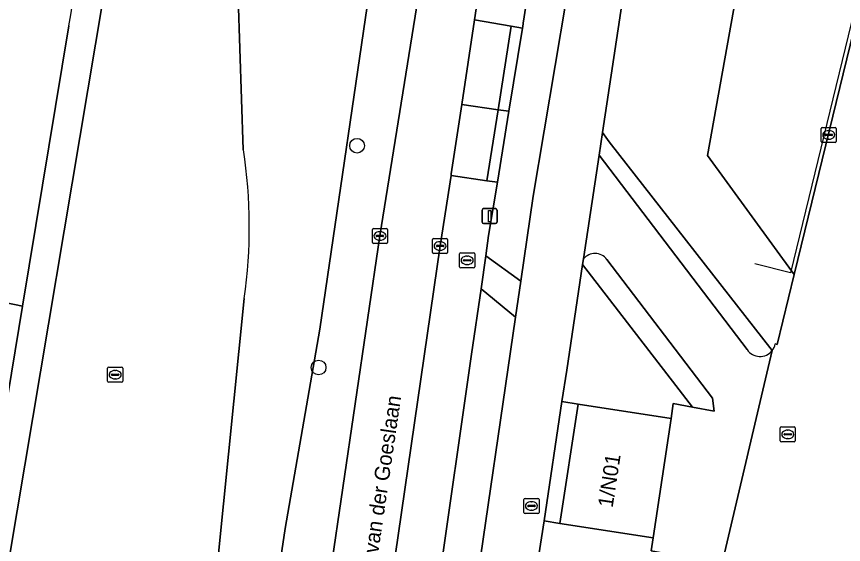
# Model space of a CAD drawing. Extents: x 163043 to 165076, y 382019 to 382874.
# Drawn here: x 163119.9 to 163174.8, y 382777.8 to 382812.9 of the extents above; entities that cross this region are included whole.
import ezdxf

# ---------------------------------------------------------------- set-up
doc = ezdxf.new("R2010")
doc.units = 0
for name, color, linetype in [('IMGEO_Berm_groen', 7, 'Continuous'), ('IMGEO_Berm_halfverhard', 7, 'Continuous'), ('IMGEO_Boom', 7, 'Continuous'), ('IMGEO_Brandkraan', 7, 'Continuous'), ('IMGEO_Erf', 7, 'Continuous'), ('IMGEO_Fietspad_gesloten', 7, 'Continuous'), ('IMGEO_Fietspad_open', 7, 'Continuous'), ('IMGEO_Groenvoorziening', 7, 'Continuous'), ('IMGEO_Hek', 7, 'Continuous'), ('IMGEO_Kolk', 7, 'Continuous'), ('IMGEO_Lichtmast', 7, 'Continuous'), ('IMGEO_Openbare_ruimte_label', 7, 'Continuous'), ('IMGEO_Pand', 7, 'Continuous'), ('IMGEO_Pand_nummerreeks', 7, 'Continuous'), ('IMGEO_Parkeervlak_open', 7, 'Continuous'), ('IMGEO_Rijbaan_lokaal_gesloten', 7, 'Continuous'), ('IMGEO_Rijbaan_lokaal_open', 7, 'Continuous'), ('IMGEO_Rioolput', 7, 'Continuous'), ('IMGEO_Voetpad_halfverhard', 7, 'Continuous'), ('IMGEO_Voetpad_open', 7, 'Continuous')]:
    doc.layers.add(name, color=color, linetype=linetype)

msp = doc.modelspace()

# ---------------------------------------------------------------- linework, layer by layer
at = {"layer": 'IMGEO_Berm_groen'}
for points in [[(163144.059, 382798.28), (163147.602, 382820.471), (163149.65, 382831.634), (163150.516, 382836.357), (163150.728, 382837.512), (163148.179, 382837.97), (163148.999, 382842.523)], [(163135.699, 382830.541), (163137.058, 382838.452), (163135.555, 382839.712), (163129.752, 382841.072), (163125.716, 382814.214), (163119.444, 382776.857), (163117.196, 382766.95)], [(163144.103, 382835.721), (163143.26, 382822.615), (163143.707, 382817.037), (163140.066, 382792.087), (163137.776, 382778.86), (163133.466, 382750), (163130.056, 382727.169), (163128.37, 382716.411), (163130.927, 382716.032), (163131.494, 382720.017), (163132.583, 382726.924)], [(163135.056, 382794.132), (163131.605, 382759.828), (163131.17, 382753.793), (163131.079, 382750), (163130.908, 382742.92), (163130.056, 382727.169), (163133.466, 382750), (163137.776, 382778.86), (163140.066, 382792.087), (163143.707, 382817.037), (163143.26, 382822.615), (163144.103, 382835.721)], [(163134.992, 382804.003), (163134.545, 382817.473)], [(163134.545, 382817.473), (163134.992, 382804.003)], [(163117.196, 382766.95), (163119.444, 382776.857), (163125.716, 382814.214)], [(163114.939, 382798.525), (163114.915, 382798.417), (163114.168, 382794.935), (163115.63, 382794.599), (163120.341, 382793.612), (163123.418, 382812.236)], [(163123.418, 382812.236), (163120.341, 382793.612), (163118.136, 382780.262)], [(163133.078, 382728.993), (163133.75, 382730.587), (163134.348, 382732.415), (163134.652, 382734.165), (163134.996, 382736.383), (163136.998, 382750), (163137.687, 382754.683), (163140.785, 382775.983), (163144.059, 382798.28)], [(163118.136, 382780.262), (163120.341, 382793.612), (163115.63, 382794.599), (163108.285, 382760.577), (163100.666, 382724.498), (163102.091, 382725.758)], [(163128.054, 382714.322), (163128.37, 382716.411), (163130.056, 382727.169), (163130.908, 382742.92), (163131.079, 382750), (163131.17, 382753.793), (163131.605, 382759.828), (163135.056, 382794.132)]]:
    msp.add_lwpolyline(points, dxfattribs=at)
for points in [[(163157.332, 382836.53), (163154.718, 382836.977), (163154.482, 382835.678), (163153.583, 382830.888), (163150.907, 382816.447), (163150.331, 382812.628), (163152.761, 382812.211), (163153.515, 382812.081), (163153.528, 382812.16), (163153.568, 382812.405)], [(163150.138, 382790.439), (163150.763, 382794.772), (163151.077, 382796.956), (163151.271, 382798.302), (163151.849, 382801.853), (163151.156, 382801.951), (163148.773, 382802.288), (163148.045, 382797.616), (163144.417, 382772.599), (163146.726, 382772.31), (163147.509, 382772.212), (163147.935, 382775.112)]]:
    msp.add_lwpolyline(points, close=True, dxfattribs=at)
for centre, radius, start, end in [((163009.489, 382831.398), 115.53, 350.45256, 356.35077), ((163009.489, 382831.398), 115.53, 350.45256, 356.35077), ((163101.746, 382798.852), 33.643, 351.9354, 8.8075), ((163101.746, 382798.852), 33.643, 351.9354, 8.8075)]:
    msp.add_arc(centre, radius, start, end, dxfattribs=at)
at = {"layer": 'IMGEO_Berm_halfverhard'}
for points in [[(163159.263, 382804.526), (163158.823, 382805.145), (163158.596, 382803.635), (163168.418, 382790.74)], [(163170.081, 382790.666), (163159.263, 382804.526)], [(163157.56, 382796.752), (163157.504, 382796.382), (163163.68, 382788.362), (163164.793, 382786.917), (163166.223, 382786.643), (163166.127, 382787.521), (163159.112, 382796.727)]]:
    msp.add_lwpolyline(points, dxfattribs=at)
for centre, radius, start, end in [((163158.326, 382796.131), 0.986, 37.1943, 140.96), ((163169.276, 382791.301), 1.025, 213.1917, 321.7126)]:
    msp.add_arc(centre, radius, start, end, dxfattribs=at)
at = {"layer": 'IMGEO_Boom'}
for centre in [(163142.541, 382804.272), (163139.988, 382789.546)]:
    msp.add_circle(centre, 0.489, dxfattribs=at)
at = {"layer": 'IMGEO_Brandkraan'}
for p, q in [((163153.685, 382780.853), (163154.537, 382780.853)), ((163153.61, 382779.927), (163153.61, 382780.779)), ((163153.869, 382780.347), (163153.869, 382780.359)), ((163154.307, 382780.31), (163153.909, 382780.31)), ((163153.912, 382780.396), (163154.31, 382780.396)), ((163154.098, 382780.633), (163154.123, 382780.633)), ((163154.353, 382780.359), (163154.353, 382780.347)), ((163154.611, 382780.779), (163154.611, 382779.927)), ((163154.537, 382779.853), (163153.685, 382779.853)), ((163154.121, 382780.073), (163154.096, 382780.073))]:
    msp.add_line(p, q, dxfattribs=at)
for points in [[(163153.685, 382780.853), (163154.537, 382780.853)], [(163153.61, 382779.927), (163153.61, 382780.779)], [(163154.611, 382780.779), (163154.611, 382779.927)], [(163154.537, 382779.853), (163153.685, 382779.853)]]:
    msp.add_lwpolyline(points, dxfattribs=at)
for centre, radius, start, end in [((163153.687, 382780.777), 0.0765, 91.552, 178.448), ((163153.687, 382780.777), 0.0765, 91.552, 178.448), ((163154.535, 382780.777), 0.0765, 1.552, 88.448), ((163154.535, 382780.777), 0.0765, 1.552, 88.448), ((163153.909, 382780.356), 0.0403, 85.8775, 175.7526), ((163153.906, 382780.346), 0.0366, 178.938, 274.7102), ((163154.31, 382780.353), 0.043, 264.8664, 352.4533), ((163154.314, 382780.358), 0.0386, 1.7309, 96.639), ((163153.687, 382779.929), 0.0765, 181.552, 268.448), ((163153.687, 382779.929), 0.0765, 181.552, 268.448), ((163154.535, 382779.929), 0.0765, 271.552, 358.448), ((163154.535, 382779.929), 0.0765, 271.552, 358.448)]:
    msp.add_arc(centre, radius, start, end, dxfattribs=at)
for centre, major_axis, ratio, start_param, end_param in [((163154.097, 382780.353), (-0.387, 0.002), 0.722429, 4.712389, 7.853982), ((163154.122, 382780.353), (-0.39, 0.002), 0.717154, 1.570796, 4.712389)]:
    msp.add_ellipse(centre, major_axis=major_axis, ratio=ratio, start_param=start_param, end_param=end_param, dxfattribs=at)
at = {"layer": 'IMGEO_Erf'}
for points in [[(163360.605, 382802.831), (163320.187, 382810.107), (163314.649, 382811.104), (163314.256, 382811.175), (163314.349, 382812.183), (163260.669, 382823.114), (163260.43, 382821.928), (163260.281, 382821.959), (163252.701, 382823.524), (163242.427, 382825.645), (163242.333, 382825.25), (163240.001, 382825.677), (163241.323, 382832.305), (163232.097, 382834.207), (163234.481, 382827.114), (163183.142, 382837.726), (163182.274, 382837.906), (163182.21, 382837.622), (163181.791, 382837.701), (163171.545, 382795.713), (163170.414, 382791.078), (163170.285, 382791.115)], [(163170.081, 382790.666), (163166.826, 382776.841), (163169.382, 382776.239), (163169.071, 382774.966), (163168.15, 382770.94), (163167.891, 382771.003), (163167.468, 382769.275), (163156.035, 382722.526), (163161.495, 382721.157), (163163.241, 382720.719), (163175.878, 382717.552), (163198.326, 382728.588), (163200.211, 382729.514), (163222.075, 382740.263), (163242.58, 382750), (163320.843, 382788.378)]]:
    msp.add_lwpolyline(points, dxfattribs=at)
msp.add_arc((163169.266, 382791.307), 1.037, 321.8058, 349.3255, dxfattribs=at)
at = {"layer": 'IMGEO_Fietspad_gesloten'}
for points in [[(163160.254, 382840.645), (163160.864, 382844.839), (163161.113, 382845.228), (163163.828, 382857.821), (163161.411, 382858.355), (163161.217, 382857.454), (163158.619, 382845.314), (163158.416, 382844.084), (163158.129, 382842.056), (163157.76, 382839.448), (163157.671, 382838.945), (163157.332, 382836.53), (163153.568, 382812.405), (163153.528, 382812.16), (163153.515, 382812.081), (163152.616, 382806.559), (163151.849, 382801.853), (163151.271, 382798.302), (163151.077, 382796.956), (163153.406, 382795.273), (163154.228, 382800.916), (163156.415, 382813.95)], [(163150.245, 382773.595), (163153.058, 382792.885), (163150.763, 382794.772), (163150.138, 382790.439), (163147.935, 382775.112), (163147.509, 382772.212), (163145.195, 382756.443), (163143.08, 382742.3), (163139.573, 382718.665), (163139.22, 382715.736), (163138.911, 382713.773), (163141.421, 382713.325), (163141.748, 382715.527), (163143.616, 382727.869), (163147.259, 382753.463)]]:
    msp.add_lwpolyline(points, close=True, dxfattribs=at)
at = {"layer": 'IMGEO_Fietspad_open'}
msp.add_lwpolyline([(163153.406, 382795.273), (163151.077, 382796.956), (163150.763, 382794.772), (163153.058, 382792.885)], close=True, dxfattribs=at)
at = {"layer": 'IMGEO_Groenvoorziening'}
for points in [[(163173.417, 382846.227), (163168.902, 382847.136), (163167.534, 382847.364), (163167.195, 382845.104), (163164.825, 382845.479), (163161.538, 382823.186), (163158.823, 382805.145), (163159.263, 382804.526), (163170.081, 382790.666)], [(163170.285, 382791.115), (163170.414, 382791.078), (163171.545, 382795.713), (163165.783, 382803.624), (163173.417, 382846.227)], [(163164.114, 382776.987), (163162.054, 382777.371), (163162.18, 382778.247), (163155.996, 382779.19), (163154.944, 382779.366), (163154.605, 382777.113), (163154.119, 382773.886)]]:
    msp.add_lwpolyline(points, dxfattribs=at)
for points in [[(163181.791, 382837.701), (163182.21, 382837.622), (163182.274, 382837.906), (163183.691, 382844.16), (163173.417, 382846.227), (163165.783, 382803.624), (163171.545, 382795.713)], [(163157.504, 382796.382), (163156.45, 382789.376), (163156.137, 382787.298), (163157.203, 382787.107), (163163.387, 382786.165), (163163.519, 382787.161), (163164.793, 382786.917), (163163.68, 382788.362)]]:
    msp.add_lwpolyline(points, close=True, dxfattribs=at)
msp.add_arc((163169.266, 382791.307), 1.037, 321.8058, 349.3255, dxfattribs=at)
at = {"layer": 'IMGEO_Hek'}
msp.add_lwpolyline([(163182.274, 382837.906), (163181.977, 382837.967), (163181.572, 382838.061), (163171.308, 382795.842), (163168.94, 382796.432)], dxfattribs=at)
at = {"layer": 'IMGEO_Kolk'}
for p, q in [((163173.336, 382804.562), (163173.336, 382805.414)), ((163173.411, 382805.488), (163174.263, 382805.488)), ((163173.595, 382804.982), (163173.595, 382804.994)), ((163173.638, 382805.031), (163174.036, 382805.031)), ((163173.824, 382805.268), (163173.849, 382805.268)), ((163174.079, 382804.994), (163174.079, 382804.982)), ((163174.337, 382805.414), (163174.337, 382804.562)), ((163174.263, 382804.488), (163173.411, 382804.488)), ((163174.033, 382804.945), (163173.635, 382804.945)), ((163173.847, 382804.708), (163173.822, 382804.708)), ((163143.557, 382797.854), (163143.557, 382798.706)), ((163143.632, 382798.78), (163144.484, 382798.78)), ((163144.045, 382798.56), (163144.07, 382798.56)), ((163144.558, 382798.706), (163144.558, 382797.854)), ((163143.816, 382798.274), (163143.816, 382798.286)), ((163144.254, 382798.237), (163143.856, 382798.237)), ((163143.859, 382798.323), (163144.257, 382798.323)), ((163144.068, 382798), (163144.043, 382798)), ((163144.3, 382798.286), (163144.3, 382798.274)), ((163147.545, 382797.19), (163147.545, 382798.042)), ((163147.62, 382798.116), (163148.472, 382798.116)), ((163148.033, 382797.896), (163148.058, 382797.896)), ((163148.546, 382798.042), (163148.546, 382797.19)), ((163144.484, 382797.78), (163143.632, 382797.78)), ((163147.804, 382797.61), (163147.804, 382797.622)), ((163148.242, 382797.573), (163147.844, 382797.573)), ((163147.847, 382797.659), (163148.245, 382797.659)), ((163148.056, 382797.336), (163148.031, 382797.336)), ((163148.288, 382797.622), (163148.288, 382797.61)), ((163148.472, 382797.116), (163147.62, 382797.116))]:
    msp.add_line(p, q, dxfattribs=at)
for points in [[(163173.336, 382804.562), (163173.336, 382805.414)], [(163173.411, 382805.488), (163174.263, 382805.488)], [(163174.337, 382805.414), (163174.337, 382804.562)], [(163174.263, 382804.488), (163173.411, 382804.488)], [(163143.557, 382797.854), (163143.557, 382798.706)], [(163143.632, 382798.78), (163144.484, 382798.78)], [(163144.558, 382798.706), (163144.558, 382797.854)], [(163147.545, 382797.19), (163147.545, 382798.042)], [(163147.62, 382798.116), (163148.472, 382798.116)], [(163148.546, 382798.042), (163148.546, 382797.19)], [(163144.484, 382797.78), (163143.632, 382797.78)], [(163148.472, 382797.116), (163147.62, 382797.116)]]:
    msp.add_lwpolyline(points, dxfattribs=at)
for centre, radius, start, end in [((163173.413, 382805.412), 0.0765, 91.552, 178.448), ((163173.413, 382805.412), 0.0765, 91.552, 178.448), ((163173.635, 382804.991), 0.0403, 85.8775, 175.7526), ((163173.632, 382804.981), 0.0366, 178.938, 274.7102), ((163174.036, 382804.988), 0.043, 264.8664, 352.4533), ((163174.04, 382804.993), 0.0386, 1.7309, 96.639), ((163174.261, 382805.412), 0.0765, 1.552, 88.448), ((163174.261, 382805.412), 0.0765, 1.552, 88.448), ((163173.413, 382804.564), 0.0765, 181.552, 268.448), ((163173.413, 382804.564), 0.0765, 181.552, 268.448), ((163174.261, 382804.564), 0.0765, 271.552, 358.448), ((163174.261, 382804.564), 0.0765, 271.552, 358.448), ((163143.634, 382798.704), 0.0765, 91.552, 178.448), ((163143.634, 382798.704), 0.0765, 91.552, 178.448), ((163144.482, 382798.704), 0.0765, 1.552, 88.448), ((163144.482, 382798.704), 0.0765, 1.552, 88.448), ((163143.634, 382797.856), 0.0765, 181.552, 268.448), ((163143.634, 382797.856), 0.0765, 181.552, 268.448), ((163143.856, 382798.283), 0.0403, 85.8775, 175.7526), ((163143.853, 382798.273), 0.0366, 178.938, 274.7102), ((163144.257, 382798.28), 0.043, 264.8664, 352.4533), ((163144.261, 382798.285), 0.0386, 1.7309, 96.639), ((163144.482, 382797.856), 0.0765, 271.552, 358.448), ((163144.482, 382797.856), 0.0765, 271.552, 358.448), ((163147.622, 382798.04), 0.0765, 91.552, 178.448), ((163147.622, 382798.04), 0.0765, 91.552, 178.448), ((163148.47, 382798.04), 0.0765, 1.552, 88.448), ((163148.47, 382798.04), 0.0765, 1.552, 88.448), ((163147.844, 382797.619), 0.0403, 85.8775, 175.7526), ((163147.841, 382797.609), 0.0366, 178.938, 274.7102), ((163148.245, 382797.616), 0.043, 264.8664, 352.4533), ((163148.249, 382797.621), 0.0386, 1.7309, 96.639), ((163147.622, 382797.192), 0.0765, 181.552, 268.448), ((163147.622, 382797.192), 0.0765, 181.552, 268.448), ((163148.47, 382797.192), 0.0765, 271.552, 358.448), ((163148.47, 382797.192), 0.0765, 271.552, 358.448)]:
    msp.add_arc(centre, radius, start, end, dxfattribs=at)
for centre, major_axis, ratio, start_param, end_param in [((163173.823, 382804.988), (-0.387, 0.002), 0.722429, 4.712389, 7.853982), ((163173.848, 382804.988), (-0.39, 0.002), 0.717154, 1.570796, 4.712389), ((163144.044, 382798.28), (-0.387, 0.002), 0.722429, 4.712389, 7.853982), ((163144.069, 382798.28), (-0.39, 0.002), 0.717154, 1.570796, 4.712389), ((163148.032, 382797.616), (-0.387, 0.002), 0.722429, 4.712389, 7.853982), ((163148.057, 382797.616), (-0.39, 0.002), 0.717154, 1.570796, 4.712389)]:
    msp.add_ellipse(centre, major_axis=major_axis, ratio=ratio, start_param=start_param, end_param=end_param, dxfattribs=at)
at = {"layer": 'IMGEO_Lichtmast'}
for p, q in [((163150.936, 382800.099), (163151.726, 382800.099)), ((163151.726, 382800.099), (163150.936, 382800.099)), ((163150.836, 382799.199), (163150.836, 382799.999)), ((163150.836, 382799.999), (163150.836, 382799.199)), ((163151.826, 382799.999), (163151.826, 382799.199)), ((163151.826, 382799.199), (163151.826, 382799.999)), ((163151.726, 382799.099), (163150.936, 382799.099)), ((163150.936, 382799.099), (163151.726, 382799.099))]:
    msp.add_line(p, q, dxfattribs=at)
msp.add_lwpolyline([(163151.256, 382799.974), (163151.406, 382799.974), (163151.406, 382799.224), (163151.256, 382799.224), (163151.256, 382799.974)], dxfattribs=at)
for centre, start, end in [((163150.936, 382799.999), 90, 180), ((163150.936, 382799.999), 90, 180), ((163151.726, 382799.999), 0, 90), ((163151.726, 382799.999), 360, 90), ((163150.936, 382799.199), 180, 270), ((163150.936, 382799.199), 180, 270), ((163151.726, 382799.199), 270, 0), ((163151.726, 382799.199), 270, 0)]:
    msp.add_arc(centre, 0.1, start, end, dxfattribs=at)
at = {"layer": 'IMGEO_Pand'}
msp.add_lwpolyline([(163163.387, 382786.165), (163157.203, 382787.107), (163155.996, 382779.19), (163162.18, 382778.247)], close=True, dxfattribs=at)
at = {"layer": 'IMGEO_Parkeervlak_open'}
msp.add_lwpolyline([(163151.891, 382806.653), (163149.485, 382807.011), (163148.791, 382802.404), (163148.773, 382802.288), (163151.156, 382801.951)], close=True, dxfattribs=at)
at = {"layer": 'IMGEO_Rijbaan_lokaal_gesloten'}
for points in [[(163148.045, 382797.616), (163148.773, 382802.288), (163148.791, 382802.404), (163149.485, 382807.011), (163150.331, 382812.628), (163150.907, 382816.447), (163153.583, 382830.888), (163149.65, 382831.634), (163147.602, 382820.471), (163144.059, 382798.28), (163140.785, 382775.983), (163137.687, 382754.683), (163136.998, 382750), (163134.996, 382736.383), (163134.652, 382734.165), (163134.348, 382732.415), (163133.75, 382730.587), (163133.078, 382728.993)], [(163132.583, 382726.924), (163131.494, 382720.017), (163130.927, 382716.032), (163135.914, 382716.104), (163136.45, 382718.692), (163137.251, 382724.043), (163138.873, 382735.001), (163141.12, 382750), (163141.714, 382753.966), (163144.417, 382772.599), (163148.045, 382797.616)]]:
    msp.add_lwpolyline(points, dxfattribs=at)
at = {"layer": 'IMGEO_Rijbaan_lokaal_open'}
for points in [[(163152.761, 382812.211), (163150.331, 382812.628), (163149.485, 382807.011), (163151.891, 382806.653)], [(163153.515, 382812.081), (163152.761, 382812.211), (163151.891, 382806.653), (163152.616, 382806.559)]]:
    msp.add_lwpolyline(points, close=True, dxfattribs=at)
for points in [[(163168.418, 382790.74), (163158.596, 382803.635), (163157.56, 382796.752)], [(163159.112, 382796.727), (163166.127, 382787.521), (163166.223, 382786.643), (163164.793, 382786.917), (163163.519, 382787.161), (163163.387, 382786.165), (163162.18, 382778.247), (163162.054, 382777.371), (163164.114, 382776.987)], [(163168.933, 382774.981), (163169.071, 382774.966), (163169.382, 382776.239), (163166.826, 382776.841), (163170.081, 382790.666)]]:
    msp.add_lwpolyline(points, dxfattribs=at)
for centre, radius, start, end in [((163158.326, 382796.131), 0.986, 37.1943, 140.96), ((163169.276, 382791.301), 1.025, 213.1917, 321.7126)]:
    msp.add_arc(centre, radius, start, end, dxfattribs=at)
at = {"layer": 'IMGEO_Rioolput'}
for p, q in [((163149.343, 382796.237), (163149.343, 382797.089)), ((163149.418, 382797.163), (163150.27, 382797.163)), ((163149.831, 382796.943), (163149.856, 382796.943)), ((163150.344, 382797.089), (163150.344, 382796.237)), ((163149.602, 382796.657), (163149.602, 382796.669)), ((163150.04, 382796.62), (163149.642, 382796.62)), ((163149.645, 382796.706), (163150.043, 382796.706)), ((163149.854, 382796.383), (163149.829, 382796.383)), ((163150.086, 382796.669), (163150.086, 382796.657)), ((163150.27, 382796.163), (163149.418, 382796.163)), ((163125.988, 382788.643), (163125.988, 382789.495)), ((163126.063, 382789.569), (163126.915, 382789.569)), ((163126.247, 382789.063), (163126.247, 382789.075)), ((163126.29, 382789.112), (163126.688, 382789.112)), ((163126.476, 382789.349), (163126.501, 382789.349)), ((163126.731, 382789.075), (163126.731, 382789.063)), ((163126.989, 382789.495), (163126.989, 382788.643)), ((163126.915, 382788.569), (163126.063, 382788.569)), ((163126.685, 382789.026), (163126.287, 382789.026)), ((163126.499, 382788.789), (163126.474, 382788.789)), ((163170.618, 382784.682), (163170.618, 382785.534)), ((163170.693, 382785.608), (163171.545, 382785.608)), ((163171.106, 382785.388), (163171.131, 382785.388)), ((163171.619, 382785.534), (163171.619, 382784.682)), ((163170.877, 382785.102), (163170.877, 382785.114)), ((163171.315, 382785.065), (163170.917, 382785.065)), ((163170.92, 382785.151), (163171.318, 382785.151)), ((163171.129, 382784.828), (163171.104, 382784.828)), ((163171.361, 382785.114), (163171.361, 382785.102)), ((163171.545, 382784.608), (163170.693, 382784.608))]:
    msp.add_line(p, q, dxfattribs=at)
for points in [[(163149.343, 382796.237), (163149.343, 382797.089)], [(163149.418, 382797.163), (163150.27, 382797.163)], [(163150.344, 382797.089), (163150.344, 382796.237)], [(163150.27, 382796.163), (163149.418, 382796.163)], [(163125.988, 382788.643), (163125.988, 382789.495)], [(163126.063, 382789.569), (163126.915, 382789.569)], [(163126.989, 382789.495), (163126.989, 382788.643)], [(163126.915, 382788.569), (163126.063, 382788.569)], [(163170.618, 382784.682), (163170.618, 382785.534)], [(163170.693, 382785.608), (163171.545, 382785.608)], [(163171.619, 382785.534), (163171.619, 382784.682)], [(163171.545, 382784.608), (163170.693, 382784.608)]]:
    msp.add_lwpolyline(points, dxfattribs=at)
for centre, radius, start, end in [((163149.42, 382797.087), 0.0765, 91.552, 178.448), ((163149.42, 382797.087), 0.0765, 91.552, 178.448), ((163150.268, 382797.087), 0.0765, 1.552, 88.448), ((163150.268, 382797.087), 0.0765, 1.552, 88.448), ((163149.42, 382796.239), 0.0765, 181.552, 268.448), ((163149.42, 382796.239), 0.0765, 181.552, 268.448), ((163149.642, 382796.666), 0.0403, 85.8775, 175.7526), ((163149.639, 382796.656), 0.0366, 178.938, 274.7102), ((163150.043, 382796.663), 0.043, 264.8664, 352.4533), ((163150.047, 382796.668), 0.0386, 1.7309, 96.639), ((163150.268, 382796.239), 0.0765, 271.552, 358.448), ((163150.268, 382796.239), 0.0765, 271.552, 358.448), ((163126.065, 382789.493), 0.0765, 91.552, 178.448), ((163126.065, 382789.493), 0.0765, 91.552, 178.448), ((163126.287, 382789.072), 0.0403, 85.8775, 175.7526), ((163126.692, 382789.074), 0.0386, 1.7309, 96.639), ((163126.913, 382789.493), 0.0765, 1.552, 88.448), ((163126.913, 382789.493), 0.0765, 1.552, 88.448), ((163126.065, 382788.645), 0.0765, 181.552, 268.448), ((163126.065, 382788.645), 0.0765, 181.552, 268.448), ((163126.284, 382789.062), 0.0366, 178.938, 274.7102), ((163126.688, 382789.069), 0.043, 264.8664, 352.4533), ((163126.913, 382788.645), 0.0765, 271.552, 358.448), ((163126.913, 382788.645), 0.0765, 271.552, 358.448), ((163170.695, 382785.532), 0.0765, 91.552, 178.448), ((163170.695, 382785.532), 0.0765, 91.552, 178.448), ((163171.543, 382785.532), 0.0765, 1.552, 88.448), ((163171.543, 382785.532), 0.0765, 1.552, 88.448), ((163170.695, 382784.684), 0.0765, 181.552, 268.448), ((163170.695, 382784.684), 0.0765, 181.552, 268.448), ((163170.917, 382785.111), 0.0403, 85.8775, 175.7526), ((163170.914, 382785.101), 0.0366, 178.938, 274.7102), ((163171.318, 382785.108), 0.043, 264.8664, 352.4533), ((163171.322, 382785.113), 0.0386, 1.7309, 96.639), ((163171.543, 382784.684), 0.0765, 271.552, 358.448), ((163171.543, 382784.684), 0.0765, 271.552, 358.448)]:
    msp.add_arc(centre, radius, start, end, dxfattribs=at)
for centre, major_axis, ratio, start_param, end_param in [((163149.83, 382796.663), (-0.387, 0.002), 0.722429, 4.712389, 7.853982), ((163149.855, 382796.663), (-0.39, 0.002), 0.717154, 1.570796, 4.712389), ((163126.475, 382789.069), (-0.387, 0.002), 0.722429, 4.712389, 7.853982), ((163126.5, 382789.069), (-0.39, 0.002), 0.717154, 1.570796, 4.712389), ((163171.105, 382785.108), (-0.387, 0.002), 0.722429, 4.712389, 7.853982), ((163171.13, 382785.108), (-0.39, 0.002), 0.717154, 1.570796, 4.712389)]:
    msp.add_ellipse(centre, major_axis=major_axis, ratio=ratio, start_param=start_param, end_param=end_param, dxfattribs=at)
at = {"layer": 'IMGEO_Voetpad_halfverhard'}
msp.add_lwpolyline([(163157.203, 382787.107), (163156.137, 382787.298), (163154.944, 382779.366), (163155.996, 382779.19)], close=True, dxfattribs=at)
at = {"layer": 'IMGEO_Voetpad_open'}
for points in [[(163161.113, 382845.228), (163160.864, 382844.839), (163160.254, 382840.645), (163156.415, 382813.95), (163154.228, 382800.916), (163153.406, 382795.273), (163153.058, 382792.885), (163150.245, 382773.595), (163147.259, 382753.463), (163143.616, 382727.869), (163141.748, 382715.527), (163141.421, 382713.325), (163141.149, 382711.595)], [(163143.965, 382707.415), (163147.261, 382706.353), (163152.251, 382704.983), (163153.695, 382704.559), (163157.061, 382703.741), (163157.36, 382705.283), (163153.872, 382706.151), (163149.001, 382707.635), (163148.756, 382707.71), (163144.559, 382708.957), (163150.553, 382750), (163151.497, 382756.461), (163153.214, 382767.874), (163154.119, 382773.886), (163154.605, 382777.113), (163154.944, 382779.366), (163156.137, 382787.298), (163156.45, 382789.376), (163157.504, 382796.382), (163157.56, 382796.752), (163158.596, 382803.635), (163158.823, 382805.145), (163161.538, 382823.186)]]:
    msp.add_lwpolyline(points, dxfattribs=at)
msp.add_lwpolyline([(163152.616, 382806.559), (163151.891, 382806.653), (163151.156, 382801.951), (163151.849, 382801.853)], close=True, dxfattribs=at)

# ---------------------------------------------------------------- texts
at = {"layer": 'IMGEO_Openbare_ruimte_label'}
msp.add_text('Hugo van der Goeslaan', height=1, rotation=81.6591, dxfattribs=at).set_placement((163143.421, 382773.637))
at = {"layer": 'IMGEO_Pand_nummerreeks'}
msp.add_text('1/N01', height=1, rotation=81.2776, dxfattribs=at).set_placement((163159.494, 382780.206))

doc.saveas('drawing.dxf')
